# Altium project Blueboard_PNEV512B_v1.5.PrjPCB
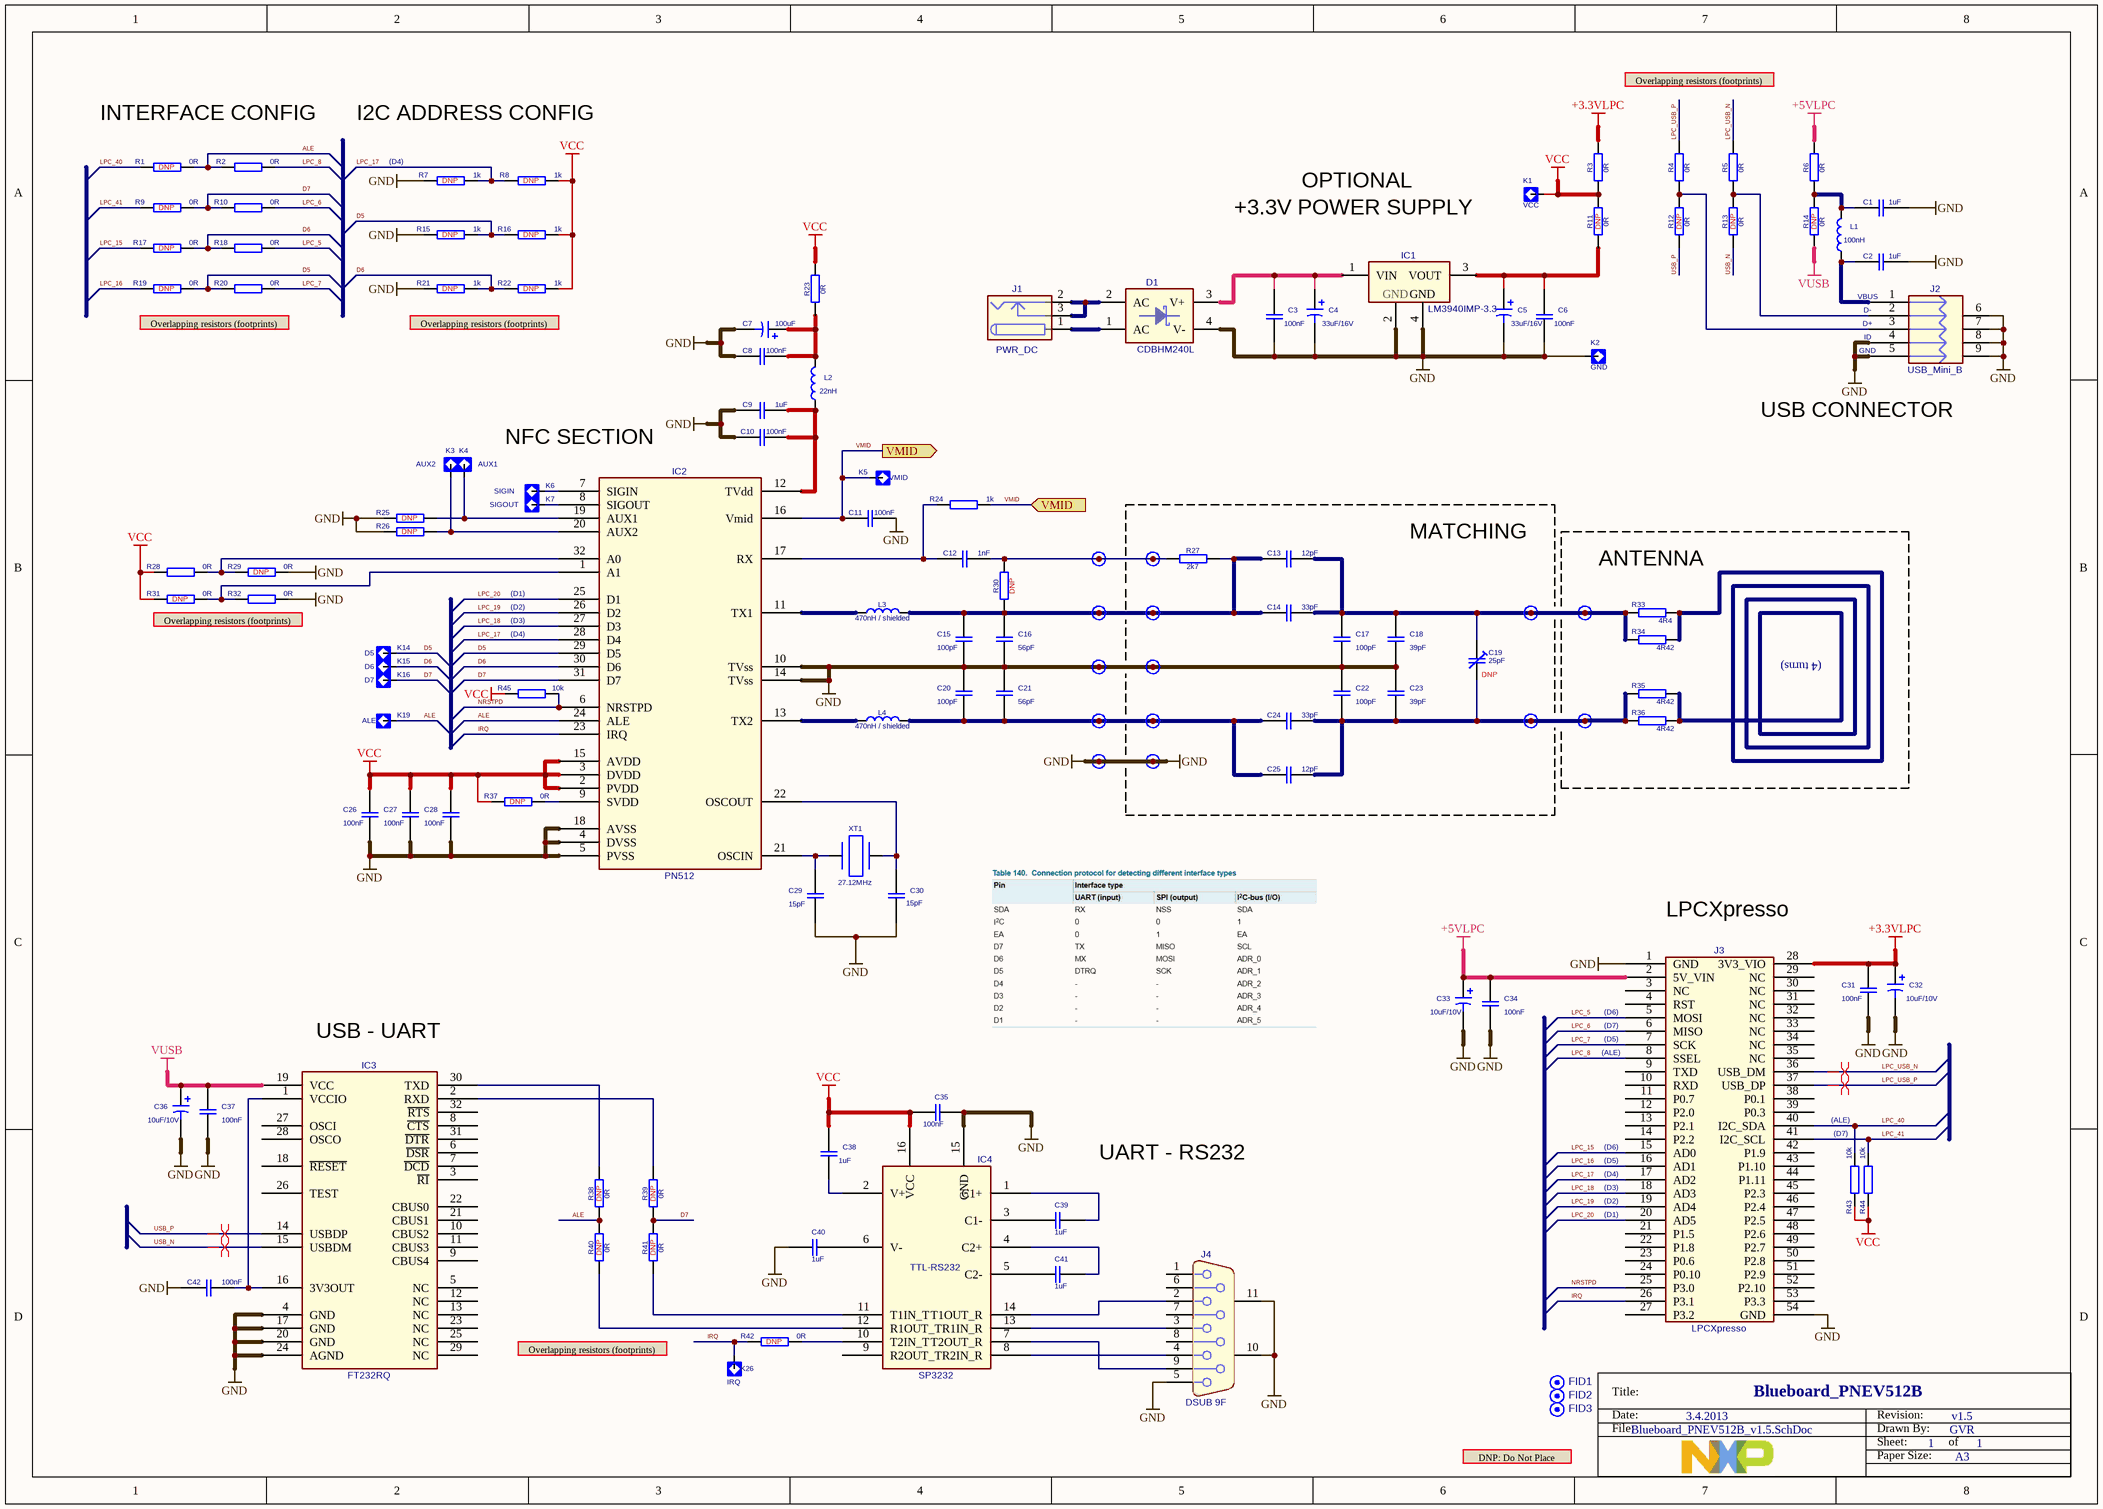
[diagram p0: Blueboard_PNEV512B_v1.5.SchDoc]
1 sheet, 131 parts. Net scope: flat (ports and power ports of the same name join across sheets).
Board file: Blueboard_PNEV512B_v1.5.PcbDoc

## Sheet Blueboard_PNEV512B_v1.5.SchDoc: Blueboard_PNEV512B
size A3; Date: 3.4.2013; DrawnBy: GVR; Address1: A3; Revision: v1.5; SheetNumber: 1; SheetTotal: 1

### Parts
?  (no value)
C1  1uF  [Y0805]
C2  1uF  [Y0805]
C3  100nF  [Y0603]
C4  33uF/16V  [C_TANTAL_B]
C5  33uF/16V  [C_TANTAL_B]
C6  100nF  [Y0603]
C7  100uF  [C_TANTAL_D]
C8  100nF  [Y0603]
C9  1uF  [Y0805]
C10  100nF  [Y0603]
C11  100nF  [Y0603]
C12  1nF  [Y0805]
C13  12pF  [Y0805]
C14  33pF  [Y0805]
C15  100pF  [Y0805]
C16  56pF  [Y0805]
C17  100pF  [Y0805]
C18  39pF  [Y0805]
C19  value 25pF  [C_TZB4_A]  (hidden comment: TZB4A 25pF)
C20  100pF  [Y0805]
C21  56pF  [Y0805]
C22  100pF  [Y0805]
C23  39pF  [Y0805]
C24  33pF  [Y0805]
C25  12pF  [Y0805]
C26  100nF  [Y0603]
C27  100nF  [Y0603]
C28  100nF  [Y0603]
C29  15pF  [Y0603]
C30  15pF  [Y0603]
C31  100nF  [Y0603]
C32  10uF/10V  [CAP_TANT_1206_CASE-A]
C33  10uF/10V  [CAP_TANT_1206_CASE-A]
C34  100nF  [Y0603]
C35  100nF  [Y0603]
C36  10uF/10V  [CAP_TANT_1206_CASE-A]
C37  100nF  [Y0603]
C38  1uF  [Y0805]
C39  1uF  [Y0805]
C40  1uF  [Y0805]
C41  1uF  [Y0805]
C42  100nF  [Y0603]
D1  CDBHM240L  [GRETZ_MBS2]
FID1  {Value}  [FIDUCIAL_40]  (value not drawn)
FID2  {Value}  [FIDUCIAL_40]  (value not drawn)
FID3  {Value}  [FIDUCIAL_40]  (value not drawn)
IC1  LM3940IMP-3.3  [SOT-223-3]
IC2  PN512  [QFN50P500X500X100-32N]
IC3  FT232RQ  [QFN-32_FTDI]
IC4  SP3232  [TSSOP-PW_16_065]
J1  value PWR_DC  [CON_JCK_2.5mm]  (hidden comment: PWR_DC_PJ-202B)
J2  USB_Mini_B  [CON_USB-B-MINI_SD-67503-010]
J3  LPCXpresso  [CON_LPCXpresso 2X27]
J4  DSUB 9F  [CON_DB9_F]
K1  value VCC  [TESTP_ROUND_1.0mm]  (hidden comment: TP1)
K2  value GND  [TESTP_ROUND_1.0mm]  (hidden comment: TP1)
K3  value AUX2  [TESTP_ROUND_1.0mm]  (hidden comment: TP1)
K4  value AUX1  [TESTP_ROUND_1.0mm]  (hidden comment: TP1)
K5  value VMID  [TESTP_ROUND_1.0mm]  (hidden comment: TP1)
K6  value SIGIN  [TESTP_ROUND_1.0mm]  (hidden comment: TP1)
K7  value SIGOUT  [TESTP_ROUND_1.0mm]  (hidden comment: TP1)
K8  TP_0.9mm  [TP_0.9mm]  (value not drawn)
K9  TP_0.9mm  [TP_0.9mm]  (value not drawn)
K10  TP_0.9mm  [TP_0.9mm]  (value not drawn)
K11  TP_0.9mm  [TP_0.9mm]  (value not drawn)
K12  TP_0.9mm  [TP_0.9mm]  (value not drawn)
K13  TP_0.9mm  [TP_0.9mm]  (value not drawn)
K14  value D5  [TESTP_ROUND_1.0mm]  (hidden comment: TP1)
K15  value D6  [TESTP_ROUND_1.0mm]  (hidden comment: TP1)
K16  value D7  [TESTP_ROUND_1.0mm]  (hidden comment: TP1)
K17  TP_0.9mm  [TP_0.9mm]  (value not drawn)
K18  TP_0.9mm  [TP_0.9mm]  (value not drawn)
K19  value ALE  [TESTP_ROUND_1.0mm]  (hidden comment: TP1)
K20  TP_0.9mm  [TP_0.9mm]  (value not drawn)
K21  TP_0.9mm  [TP_0.9mm]  (value not drawn)
K22  TP_0.9mm  [TP_0.9mm]  (value not drawn)
K23  TP_0.9mm  [TP_0.9mm]  (value not drawn)
K24  TP_0.9mm  [TP_0.9mm]  (value not drawn)
K25  TP_0.9mm  [TP_0.9mm]  (value not drawn)
K26  value IRQ  [TESTP_ROUND_1.0mm]  (hidden comment: TP1)
L1  100nH  [INDCC_1812]
L2  22nH  [Y0805]
L3  value 470nH / shielded  [INDCC_1812]  (hidden comment: 470nH / shielded (1210))
L4  value 470nH / shielded  [INDCC_1812]  (hidden comment: 470nH / shielded (1210))
R1  value 0R  [Y0805]  (hidden comment: 0R DNP)
R2  0R  [Y0805]
R3  0R  [Y0805]
R4  0R  [Y0805]
R5  0R  [Y0805]
R6  0R  [Y0805]
R7  value 1k  [Y0805]  (hidden comment: 1k DNP)
R8  value 1k  [Y0805]  (hidden comment: 1k DNP)
R9  value 0R  [Y0805]  (hidden comment: 0R DNP)
R10  0R  [Y0805]
R11  value 0R  [Y0805]  (hidden comment: 0R DNP)
R12  value 0R  [Y0805]  (hidden comment: 0R DNP)
R13  value 0R  [Y0805]  (hidden comment: 0R DNP)
R14  value 0R  [Y0805]  (hidden comment: 0R DNP)
R15  value 1k  [Y0805]  (hidden comment: 1k DNP)
R16  value 1k  [Y0805]  (hidden comment: 1k DNP)
R17  value 0R  [Y0805]  (hidden comment: 0R DNP)
R18  0R  [Y0805]
R19  value 0R  [Y0805]  (hidden comment: 0R DNP)
R20  0R  [Y0805]
R21  value 1k  [Y0805]  (hidden comment: 1k DNP)
R22  value 1k  [Y0805]  (hidden comment: 1k DNP)
R23  0R  [Y0805]
R24  1k  [Y0805]
R25  DNP  [Y0805]
R26  DNP  [Y0805]
R27  2k7  [Y0805]
R28  0R  [Y0805]
R29  value 0R  [Y0805]  (hidden comment: 0R DNP)
R30  DNP  [Y0805]
R31  value 0R  [Y0805]  (hidden comment: 0R DNP)
R32  0R  [Y0805]
R33  value 4R4  [Y0805]  (hidden comment: 4R42)
R34  4R42  [Y0805]
R35  4R42  [Y0805]
R36  4R42  [Y0805]
R37  value 0R  [Y0805]  (hidden comment: 0R DNP)
R38  value 0R  [Y0805]  (hidden comment: 0R DNP)
R39  value 0R  [Y0805]  (hidden comment: 0R DNP)
R40  value 0R  [Y0805]  (hidden comment: 0R DNP)
R41  value 0R  [Y0805]  (hidden comment: 0R DNP)
R42  value 0R  [Y0805]  (hidden comment: 0R DNP)
R43  10k  [Y0805]
R44  10k  [Y0805]
R45  10k  [Y0805]
XT1  27.12MHz  [QUARTZ_32SMX]

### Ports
VMID (in), VMID (out)

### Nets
+3.3VLPC: C31.2 C32.1 J3.28(3V3_VIO) R3.2
+5VLPC: C33.1 C34.2 J3.2(5V_VIN) R6.2
GND: C1.1 C2.1 C3.2 C4.2 C5.2 C6.2 C7.2 C8.1 C9.1 C10.1 C11.2 C15.1 C16.1 C17.1 C18.1 C20.2 C21.2 C22.2 C23.2 C26.1 C27.1 C28.1 C29.1 C30.1 C31.1 C32.2 C33.2 C34.1 C35.2 C36.2 C37.1 C40.2 C42.1 D1.4(V-) IC1.2(GND) IC1.4(GND) IC2.4(DVSS) IC2.5(PVSS) IC2.10(TVss) IC2.14(TVss) IC2.18(AVSS) IC3.4(GND) IC3.17(GND) IC3.20(GND) IC3.24(AGND) IC4.15(GND) J2.4(ID) J2.5(GND) J2.6(Case1) J2.7(Case2) J2.8(Case3) J2.9(Case4) J3.1(GND) J3.54(GND) J4.5 J4.10(GND) J4.11(GND) K2.1 K17.1 K18.1 K24.1 K25.1 R7.1 R15.1 R21.1 R25.1 R26.1 R29.2 R32.2
VCC: C26.2 C27.2 C28.2 C35.1 C38.1 IC2.2(PVDD) IC2.3(DVDD) IC2.15(AVDD) IC4.16(VCC) K1.1 R3.1 R8.2 R11.2 R16.2 R22.2 R23.2 R28.1 R31.1 R37.1 R43.1 R44.1 R45.1
VUSB: C36.1 C37.2 IC3.19(VCC) R14.1
ALE: IC2.24(ALE) K19.1 R1.2 R2.1 R38.1 R40.2
D5: IC2.29(D5) K14.1 R15.2 R16.1 R19.2 R20.1
D6: IC2.30(D6) K15.1 R17.2 R18.1 R21.2 R22.1
D7: IC2.31(D7) K16.1 R9.2 R10.1 R39.1 R41.2
IRQ: IC2.23(IRQ) J3.26(P3.1) K26.1 R42.1
LPC_5: J3.5(MOSI) R18.2
LPC_6: J3.6(MISO) R10.2
LPC_7: J3.7(SCK) R20.2
LPC_8: J3.8(SSEL) R2.2
LPC_15: J3.15(AD0) R17.1
LPC_16: J3.16(AD1) R19.1
LPC_17: IC2.28(D4) J3.17(AD2) R7.2 R8.1
LPC_18: IC2.27(D3) J3.18(AD3)
LPC_19: IC2.26(D2) J3.19(AD4)
LPC_20: IC2.25(D1) J3.20(AD5)
LPC_40: J3.40(I2C_SDA) R1.1 R43.2
LPC_41: J3.41(I2C_SCL) R9.1 R44.2
LPC_USB_N: J3.36(USB_DM) R5.2
LPC_USB_P: J3.37(USB_DP) R4.2
NRSTPD: IC2.6(NRSTPD) J3.25(P3.0) R45.2
USB_N: IC3.15(USBDM) R13.1
USB_P: IC3.14(USBDP) R12.1
VMID: C11.1 IC2.16(Vmid) K5.1 R24.2 ; port VMID
NetC1_2: C1.2 L1.2 R6.1 R14.2
NetC2_2: C2.2 J2.1(VBUS) L1.1
NetC3_1: C3.1 C4.1 D1.3(V+) IC1.1(VIN)
NetC5_1: C5.1 C6.1 IC1.3(VOUT) R11.1
NetC7_1: C7.1 C8.2 L2.2 R23.1
NetC9_2: C9.2 C10.2 IC2.12(TVdd) L2.1
NetC12_1: C12.1 IC2.17(RX) R24.1
NetC12_2: C12.2 K8.1 K9.1 R27.2 R30.1
NetC13_1: C13.1 C14.1 C15.2 C16.2 K10.1 K11.1 L3.2 R27.1 R30.2
NetC13_2: C13.2 C14.2 C17.2 C18.2 C19.1 K12.1 K13.1 R33.2 R34.2
NetC19_2: C19.2 C22.1 C23.1 C24.2 C25.2 K22.1 K23.1 R35.2 R36.2
NetC20_1: C20.1 C21.1 C24.1 C25.1 K20.1 K21.1 L4.2
NetC29_2: C29.2 IC2.21(OSCIN) XT1.1
NetC30_2: C30.2 IC2.22(OSCOUT) XT1.3
NetC38_2: C38.2 IC4.2(V+)
NetC39_1: C39.1 IC4.1(C1+)
NetC39_2: C39.2 IC4.3(C1-)
NetC40_1: C40.1 IC4.6(V-)
NetC41_1: C41.1 IC4.4(C2+)
NetC41_2: C41.2 IC4.5(C2-)
NetC42_2: C42.2 IC3.1(VCCIO) IC3.16(3V3OUT)
NetD1_1: D1.1(AC) J1.1
NetD1_2: D1.2(AC) J1.2 J1.3
NetIC2_1: IC2.1(A1) R31.2 R32.1
NetIC2_7: IC2.7(SIGIN) K6.1
NetIC2_8: IC2.8(SIGOUT) K7.1
NetIC2_9: IC2.9(SVDD) R37.2
NetIC2_11: IC2.11(TX1) L3.1
NetIC2_13: IC2.13(TX2) L4.1
NetIC2_19: IC2.19(AUX1) K4.1 R25.2
NetIC2_20: IC2.20(AUX2) K3.1 R26.2
NetIC2_32: IC2.32(A0) R28.2 R29.1
NetIC3_2: IC3.2(RXD) R39.2
NetIC3_30: IC3.30(TXD) R38.2
NetIC4_7: IC4.7(T2OUT_R) J4.9
NetIC4_8: IC4.8(R2IN_R) J4.4
NetIC4_10: IC4.10(T2IN_T) R42.2
NetIC4_11: IC4.11(T1IN_T) R41.1
NetIC4_12: IC4.12(R1OUT_T) R40.1
NetIC4_13: IC4.13(R1IN_R) J4.3
NetIC4_14: IC4.14(T1OUT_R) J4.2
NetJ2_2: J2.2(D-) R5.1 R13.2
NetJ2_3: J2.3(D+) R4.1 R12.2
NetR33_1: R33.1 R34.1 R35.1 R36.1

Not connected (* = marked no-connect by the designer): FID1 1; FID2 1; FID3 1; IC3 3(~{RI}) 5(NC) 6(~{DSR}) 7(~{DCD}) 8(~{CTS}) 9(CBUS4) 10(CBUS2) 11(CBUS3) 12(NC) 13(NC) 18(~{RESET}) 21(CBUS1) 22(CBUS0) 23(NC) 25(NC) 26(TEST) 27(OSCI) 28(OSCO) 29(NC) 31(~{DTR}) 32(~{RTS}); IC4 9(R2OUT_T); J3 3(NC) 4(RST) 9(TXD) 10(RXD) 11(P0.7) 12(P2.0) 13(P2.1) 14(P2.2) 21(P1.5) 22(P1.8) 23(P0.6) 24(P0.10) 27(P3.2) 29(NC) 30(NC) 31(NC) 32(NC) 33(NC) 34(NC) 35(NC) 38(P0.1) 39(P0.3) 42(P1.9) 43(P1.10) 44(P1.11) 45(P2.3) 46(P2.4) 47(P2.5) 48(P2.6) 49(P2.7) 50(P2.8) 51(P2.9) 52(P2.10) 53(P3.3); J4 1 6 7 8; XT1 2 4

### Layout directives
differential pair: LPC_USB_N, LPC_USB_P, USB_N, USB_P

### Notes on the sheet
- Overlapping resistors (footprints)
- INTERFACE CONFIG
- I2C ADDRESS CONFIG
- (near R7) (D4)
- +3.3V POWER SUPPLY
- OPTIONAL
- D-
- VBUS
- (near J2) GND
- (near J2) ID
- (near J2) D+
- NFC SECTION
- (near J2) USB CONNECTOR
- MATCHING
- ANTENNA
- (D1)
- (D2)
- (D3)
- (D4)
- (4 turns)
- (near J3) LPCXpresso
- (near IC3) USB - UART
- (near J3) (D6)
- (near J3) (D5)
- (near J3) (D7)
- (near J3) (ALE)
- (ALE)
- UART - RS232
- (near J3) (D3)
- (near J3) (D4)
- (D7)
- (near J3) (D1)
- (near J3) (D2)
- DNP: Do Not Place

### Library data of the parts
? = Title Block NXP
C1 C2 C9 C12-C17 C20-C22 C24 C25 C38-C41 = CAPC0805
C3 C6 C8 C10 C11 C26-C31 C34 C35 C37 C42 = CAPC0603
C4 C5 = C_TANTAL_B
C7 = C_TANTAL_D
C18 C23 = CAPC0805: Value: DNP
C19 = C_TRIMM
C32 C33 C36 = C_TANTAL_1206
D1 = GRETZ_MBS2: GRETZ_MBS2_Schottky
FID1-FID3 = FIDUCIAL: FIDUCAL
IC1 = LM3940-3.3
IC3 = FT232R
J1 = CON_JCK_2.5mm: PWR_JACK_2.5mm x 5.5mm
J2 = CON_USB_B_RA: Value: 548190572 (DigiKey); Value: 675031020 (DigiKey)
J3 = CON_LPCXpresso: CON_LPCXpresso 2X27
J4 = CON_DB9_F: DB9_FEMALE; IC: 5504F1-09S-01-03
L1 L3 L4 = INDC1812
L2 = INDC0805
R1-R45 = RESC0805
XT1 = QUARTZ_32SMX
